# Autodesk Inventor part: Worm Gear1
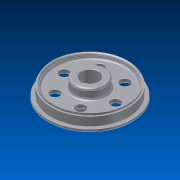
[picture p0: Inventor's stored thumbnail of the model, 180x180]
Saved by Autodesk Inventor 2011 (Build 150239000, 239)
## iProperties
Created: 2011-05
Part Number: Worm Gear1
Material: Steel, Mild
Document SubType Name: Modeling
Designer: 904Chiaki
Categories: <?xml version="1.0" encoding="UTF-16"?> <MemberInstance><Categories><FamilyTemplate><FamilyTemplateParameter ValueType="xs:double" Id="1" ObjectReferenceKey="da
Density: 7.86 g/cm^3
Mass: 36271.6 g
Surface Area: 4778.59 cm^2
Volume: 4614.7 cm^3
CustomPartVersion: 1
Author: 904Chiaki
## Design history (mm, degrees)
mirror "Mirror1"
body "Solid1"
  node "Keyway2"
sketch "Sketch12"
  geometry: C1 r 40 at (0, 0) reference; C2 r 70 at (0, 0) reference
extrude "Extrusion4" join sketch "Sketch12" distance "d116" = 24; taper "d117" = 0 deg
sketch "Sketch13"
  geometry: C1 r 40 at (0, 0) reference; C2 r 70 at (0, 0) reference
extrude "Extrusion5" join sketch "Sketch13" distance "d118" = 24; taper "d119" = 0 deg
chamfer "Chamfer2" distance "d120" = 2; stored, may be unused: second distance "d121" = 2, angle "d122" = 45 deg
fillet "Fillet4" dims "d123" = 8
workaxis "Work Axis2"
workaxis "Work Axis3"
workplane "Work Plane17"
feature "Hub Keyway"
workaxis "Work Axis4"
workplane "Work Plane18"
sketch "Sketch9"
  geometry: C1 r 162 at (0, 0); C2 r 70 at (0, 0); A1 r 199.127 centre (0, 0) between (0, 199.127) and (0, 199.127) reference
  constraints: 2 centre point, 2 coincident
  dimensions: "d94" = 324 diameter of C1; "d95" = 140 diameter of C2
extrude "Extrusion1" cut sketch "Sketch9" distance "d96" = 21; taper "d97" = 0 deg
workplane "Work Plane16"
sketch "Sketch10"
  geometry: C1 r 70 at (0, 0) reference; C2 r 40 at (0, 0)
  constraints: 1 centre point, 1 coincident
  dimensions: "d99" = 80 diameter of C2
extrude "Extrusion2" cut sketch "Sketch10" stored distance "d100" = 21; taper "d101" = 0 deg
sketch "Sketch11" dims "d102" = 232
  geometry: C1 r 70 at (0, 0) reference; C2 r 162 at (0, 0) reference; C3 r 22.5 at (116, 0); C4 r 22.5 at (58, 100.459); C5 r 22.5 at (-58, 100.459); C6 r 22.5 at (-116, 0); C7 r 22.5 at (-58, -100.459); C8 r 22.5 at (58, -100.459); 1 further point
  constraints: 6 centre point, 1 coincident, 1 horizontal alignment, 15 other
  dimensions: "d103" = 45 diameter of C3; "d106" = 360 deg dimension on C1.centre C3.centre (derived)
extrude "Extrusion3" cut sketch "Sketch11" stored distance "d108" = 21; taper "d109" = 0 deg
fillet "Fillet3" dims "d115" = 1
workplane "Work Plane13"
workplane "Work Plane14"
workplane "Work Plane15"
sketch "Base Body Sketch"
  geometry: L1 (0, -42)-(0, 42) reference; L2 (0, 30)-(170, 30); L3 (0, -30)-(190, -30) reference; L4 (0, 30)-(0, -30); L5 (170, 30)-(170, 20); L6 (175, 20)-(170, 20); L7 (190, -20)-(190, -30); L8 (190, -20)-(175, -20); L9 (175, -20)-(175, 20)
  constraints: 16 end point, 1 collinear, 1 horizontal, 1 perpendicular, 1 other
  dimensions: "d92" = 60 distance of L2.start L3.start (= da_b); "d142" = 15 distance of L7.start L8.end
revolve "Base Body2" sketch "Base Body Sketch" stored, may be unused: angle "d90" = 90 deg
revolve "Base Body" stored, may be unused: angle "d35" = 90 deg
node "Tooth Plane"
other parameters: "da_aw" = 238.5 [user parameter; used in 2 equation terms], "da_fi" = 6.51099 [user parameter], "da_b" = 60 [user parameter; used in 1 equation term], "da_df" = 374.4 [user parameter], "da_da" = 414 [user parameter], "da_beta" = 2.18669 [user parameter; used in 1 equation term], "da_alfat" = 20 deg [user parameter], "da_df1" = 59.4 [user parameter], "da_da1" = 99 [user parameter], "da_d1" = 81 [user parameter], "da_px" = 162 deg [user parameter], "d37" = -2.18669 (computed from da_rightdir, da_beta), "d68" = 238.5 (= da_aw), "d69" = 0, "d73" = 0, "d75" = 0.714 (computed from da_z), "da_dw" = 396 [user parameter], "da_rightdir" = 0 [user parameter; used in 1 equation term], "d80" = 0, "d81" = 0, "d82" = 0, "d83" = 0.714 (computed from da_z), "d84" = 0, "d85" = 180 deg, "d86" = 238.5 (= da_aw), "da_dae" = 423 [user parameter], "d124" = 90 deg
